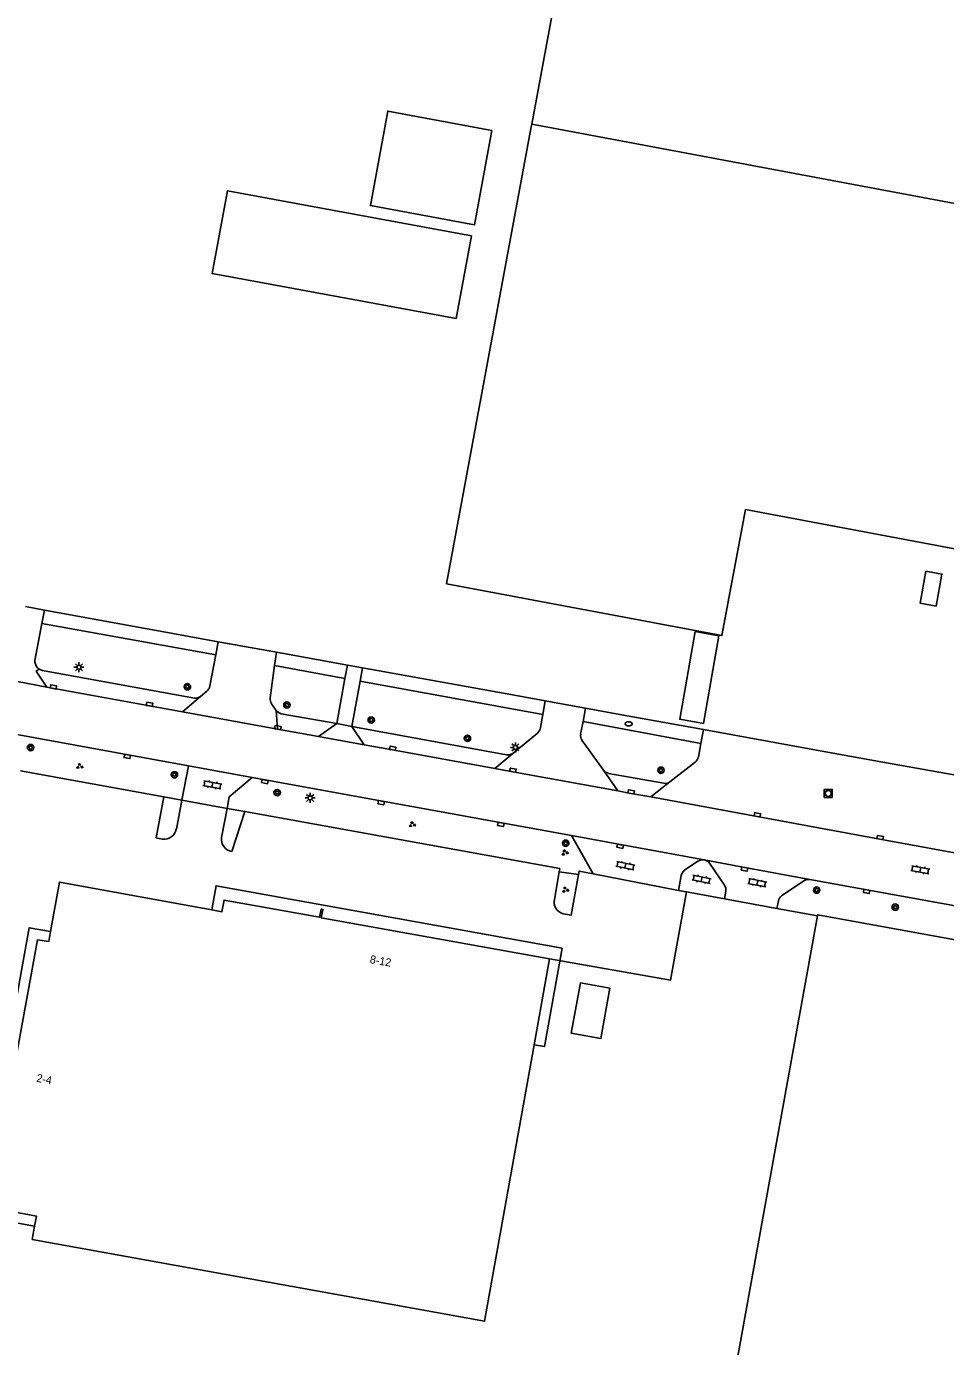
# Model space of a CAD drawing. Extents: x 130998 to 133001, y 398999 to 403002.
# Drawn here: x 132416.4 to 132531.2, y 399316.5 to 399481.4 of the extents above; entities that cross this region are included whole.
import ezdxf

# ---------------------------------------------------------------- set-up
doc = ezdxf.new("R2010")
doc.units = 0
for name, color, linetype in [('gg-afsc-hekwerk', 7, 'Continuous'), ('gg-anno-huisnummerreeks BGT', 7, 'Continuous'), ('gg-bbg-bijgebouw', 7, 'Continuous'), ('gg-bbg-gedigitaliseerde bijgebouw', 7, 'Continuous'), ('gg-bbg-hoofdgebouw', 7, 'Continuous'), ('gg-bbg-luifel en loopbrug', 7, 'Continuous'), ('gg-bbg-tussenscheiding', 7, 'Continuous'), ('gg-knt-verharding', 7, 'Continuous'), ('gg-knt-verharding nz', 7, 'Continuous'), ('gt-grn-groengrens', 7, 'Continuous'), ('gt-grn-vlakafsluiter', 7, 'Continuous'), ('gt-grn-weggrens', 7, 'Continuous'), ('gt-symb-boom', 7, 'Continuous'), ('gt-symb-brandkraan', 7, 'Continuous'), ('gt-symb-groenvak', 7, 'Continuous'), ('gt-symb-klinker verharding', 7, 'Continuous'), ('gt-symb-kolk', 7, 'Continuous'), ('gt-symb-lichtmast', 7, 'Continuous'), ('gt-symb-rioolschacht', 7, 'Continuous')]:
    doc.layers.add(name, color=color, linetype=linetype)

# ---------------------------------------------------------------- blocks, each defined once
blk = doc.blocks.new('gt0-BOOM')
at = {"layer": 'gt-symb-boom'}
for radius in [0.4, 0.2]:
    blk.add_circle((0, 0), radius, dxfattribs=at)
blk = doc.blocks.new('gt0-KOLK')
at = {"layer": 'gt-symb-kolk'}
blk.add_lwpolyline([(0, 0), (0.37, 0), (0.37, 0.4), (-0.38, 0.4), (-0.38, 0), (0, 0)], dxfattribs=at)
blk = doc.blocks.new('gt0-LMAST')
at = {"layer": 'gt-symb-lichtmast'}
for p, q in [((-0.18, 0.17), (-0.45, 0.44)), ((-0.01, 0.25), (-0.01, 0.62)), ((0.17, 0.17), (0.44, 0.44)), ((-0.26, 0), (-0.63, 0)), ((-0.18, -0.18), (-0.45, -0.45)), ((-0.01, -0.25), (-0.01, -0.63)), ((0.44, -0.45), (0.17, -0.18)), ((0.24, 0), (0.62, 0))]:
    blk.add_line(p, q, dxfattribs=at)
blk.add_circle((-0.01, 0), 0.25, dxfattribs=at)
blk = doc.blocks.new('gt0-BR')
at = {"layer": 'gt-symb-brandkraan'}
for centre, radius, start, end in [((-0.24, 0), 0.206, 107.5669, 252.4331), ((0.6, -2.66), 3, 106.892, 107.5669), ((0, -0.69), 0.938, 73.108, 106.892), ((-0.6, -2.66), 3, 72.4331, 73.108), ((0.24, 0), 0.206, 287.567, 72.4331), ((0.6, 2.66), 3, 252.4331, 253.108), ((0, 0.69), 0.938, 253.108, 286.8921), ((-0.6, 2.66), 3, 286.8921, 287.567)]:
    blk.add_arc(centre, radius, start, end, dxfattribs=at)
blk = doc.blocks.new('gt0-RS')
at = {"layer": 'gt-symb-rioolschacht'}
blk.add_lwpolyline([(-0.5, -0.5), (0.5, -0.5), (0.5, 0.5), (-0.5, 0.5)], close=True, dxfattribs=at)
blk.add_circle((0, 0), 0.375, dxfattribs=at)
blk = doc.blocks.new('gt0-GRVAK')
at = {"layer": 'gt-symb-groenvak'}
for p, q in [((-0.11, 0.19), (-0.23, 0.24)), ((-0.18, 0.15), (0.09, 0.15)), ((-0.09, 0.21), (-0.16, 0.32)), ((-0.05, 0.21), (-0.05, 0.39)), ((0, 0.21), (0.06, 0.32)), ((0.01, 0.19), (0.13, 0.24)), ((0.26, -0.05), (0.2, 0.06)), ((0.3, -0.05), (0.3, 0.13)), ((0.35, -0.05), (0.41, 0.06)), ((-0.24, -0.23), (-0.36, -0.18)), ((-0.32, -0.26), (-0.05, -0.26)), ((-0.23, -0.21), (-0.29, -0.09)), ((-0.18, -0.2), (-0.18, -0.02)), ((-0.14, -0.21), (-0.07, -0.09)), ((-0.12, -0.23), (0, -0.18)), ((0.24, -0.07), (0.12, -0.02)), ((0.17, -0.11), (0.44, -0.11)), ((0.37, -0.07), (0.49, -0.02))]:
    blk.add_line(p, q, dxfattribs=at)
blk = doc.blocks.new('gt0-KL1')
at = {"layer": 'gt-symb-klinker verharding'}
for p, q in [((-1.15, 0.3), (1.15, 0.3)), ((-1, -0.3), (-1, 0.3)), ((-0.5, 0.3), (-0.5, 0.45)), ((0, -0.3), (0, 0.3)), ((0.5, 0.3), (0.5, 0.45)), ((1, -0.3), (1, 0.3)), ((-1.15, -0.3), (1.15, -0.3)), ((-0.5, -0.45), (-0.5, -0.3)), ((0.5, -0.45), (0.5, -0.3))]:
    blk.add_line(p, q, dxfattribs=at)

msp = doc.modelspace()

# ---------------------------------------------------------------- linework, layer by layer
at = {"layer": 'gg-afsc-hekwerk'}
for p, q in [((132418.61, 399408.47), (132416.24, 399408.9)), ((132432.6, 399405.92), (132418.61, 399408.47)), ((132440.33, 399404.52), (132432.6, 399405.92)), ((132447.16, 399403.28), (132440.33, 399404.52)), ((132447.62, 399403.2), (132447.16, 399403.28)), ((132456.47, 399401.59), (132447.62, 399403.2)), ((132458.36, 399401.25), (132456.47, 399401.59)), ((132462.05, 399400.58), (132458.36, 399401.25)), ((132462.05, 399400.58), (132477.33, 399397.82)), ((132481.2, 399397.12), (132477.33, 399397.82)), ((132484.14, 399396.59), (132481.2, 399397.12)), ((132484.14, 399396.59), (132486.24, 399396.21)), ((132486.24, 399396.21), (132490.52, 399395.43)), ((132490.52, 399395.43), (132500.96, 399393.54)), ((132500.96, 399393.54), (132517.36, 399390.57)), ((132523.39, 399389.48), (132517.36, 399390.57)), ((132523.39, 399389.48), (132532.5, 399387.85)), ((132503.59, 399372.4), (132498.84, 399373.27)), ((132510.13, 399371.21), (132503.59, 399372.4)), ((132515.21, 399370.29), (132510.13, 399371.21))]:
    msp.add_line(p, q, dxfattribs=at)
msp.add_lwpolyline([(132481.74, 399364.89), (132496.83, 399362.22), (132498.84, 399373.27)], dxfattribs=at)
at = {"layer": 'gg-bbg-bijgebouw'}
msp.add_lwpolyline([(132479.5, 399469.15), (132486.41, 399506.55), (132504.29, 399503.24)], dxfattribs=at)
at = {"layer": 'gg-bbg-gedigitaliseerde bijgebouw'}
for points in [[(132474.53, 399468.38), (132461.52, 399470.79), (132459.34, 399458.99), (132472.35, 399456.58), (132474.53, 399468.38)], [(132470.05, 399444.89), (132439.57, 399450.52), (132441.48, 399460.85), (132471.96, 399455.22), (132470.05, 399444.89)]]:
    msp.add_lwpolyline(points, dxfattribs=at)
at = {"layer": 'gg-bbg-hoofdgebouw'}
for p, q in [((132515.21, 399370.29), (132501.01, 399291.82)), ((132479.81, 399354.18), (132481.74, 399364.89)), ((132417.38, 399331.51), (132417.08, 399329.85))]:
    msp.add_line(p, q, dxfattribs=at)
for points in [[(132479.5, 399469.15), (132479.45, 399468.82), (132468.86, 399411.76), (132503.27, 399405.29), (132506.22, 399421.01), (132537.65, 399415.11), (132534.89, 399400.38), (132535.88, 399400.2), (132536.06, 399401.18), (132568.46, 399395.22), (132568.28, 399394.24), (132569.27, 399394.05), (132579.82, 399450.35)], [(132439.52, 399371.03), (132420.48, 399374.48), (132419.38, 399368.31)], [(132481.74, 399364.89), (132453.21, 399370.04), (132453.42, 399371.08), (132453.2, 399371.12), (132452.98, 399370.1), (132441.07, 399372.25), (132440.8, 399370.79), (132439.52, 399371.03)], [(132515.21, 399370.29), (132515.23, 399370.38), (132564.7, 399361.42)], [(132419.38, 399368.31), (132419.15, 399367.06), (132417.77, 399367.28), (132411.63, 399333.87), (132417.61, 399332.77), (132417.38, 399331.51)], [(132417.08, 399329.85), (132473.59, 399319.63), (132479.81, 399354.18)]]:
    msp.add_lwpolyline(points, dxfattribs=at)
at = {"layer": 'gg-bbg-luifel en loopbrug'}
for points in [[(132528.76, 399413.33), (132530.75, 399412.97), (132530.03, 399408.97), (132528.04, 399409.32), (132528.76, 399413.33)], [(132500.96, 399394.29), (132502.9, 399405.24), (132499.94, 399405.77), (132497.99, 399394.82), (132500.96, 399394.29)], [(132439.52, 399371.03), (132440.07, 399374.04), (132483.3, 399366.22), (132481.08, 399353.95), (132479.81, 399354.18)], [(132417.38, 399331.51), (132410.21, 399332.8), (132416.72, 399368.79), (132419.38, 399368.31)], [(132485.58, 399361.89), (132484.44, 399355.61), (132488.14, 399354.94), (132489.28, 399361.22), (132485.58, 399361.89)]]:
    msp.add_lwpolyline(points, dxfattribs=at)
at = {"layer": 'gg-bbg-tussenscheiding'}
msp.add_line((132479.5, 399469.15), (132533.05, 399459.11), dxfattribs=at)
at = {"layer": 'gg-knt-verharding'}
for p, q in [((132418.61, 399408.47), (132418.29, 399406.79)), ((132418.29, 399406.79), (132440.02, 399402.89)), ((132440.33, 399404.52), (132440.02, 399402.89)), ((132440.02, 399402.89), (132439.27, 399399)), ((132447.62, 399403.2), (132447.37, 399401.54)), ((132447.37, 399401.54), (132446.83, 399397.5)), ((132447.37, 399401.54), (132456.17, 399399.93)), ((132455.15, 399394.28), (132456.17, 399399.93)), ((132458.07, 399399.6), (132457.03, 399393.94)), ((132480.89, 399395.41), (132458.07, 399399.6)), ((132438.9, 399398.35), (132438.13, 399397.68)), ((132447, 399396.76), (132447.58, 399395.94)), ((132480.89, 399395.41), (132481.2, 399397.12)), ((132485.92, 399394.54), (132486.24, 399396.21)), ((132448.2, 399395.51), (132455.15, 399394.28)), ((132480.59, 399393.79), (132480.89, 399395.41)), ((132485.92, 399394.54), (132485.61, 399392.96)), ((132485.92, 399394.54), (132500.64, 399391.82)), ((132436.6, 399389), (132409.08, 399394.02)), ((132457.03, 399393.94), (132476.36, 399390.4)), ((132477.13, 399390.55), (132480.22, 399393.11)), ((132500.64, 399391.82), (132500.96, 399393.54)), ((132485.78, 399392.2), (132488.45, 399388.48)), ((132500.32, 399390.1), (132500.64, 399391.82)), ((132496.76, 399387), (132499.92, 399389.45)), ((132415.64, 399388.37), (132433.52, 399385.15)), ((132436.6, 399389), (132435.79, 399384.73)), ((132489.1, 399388.07), (132496, 399386.83)), ((132444.59, 399387.55), (132484.46, 399380.29)), ((132435.79, 399384.73), (132435.1, 399381.1)), ((132441.44, 399383.7), (132440.75, 399380.04)), ((132442.04, 399378.32), (132443.67, 399383.29)), ((132443.67, 399383.29), (132483, 399376.19)), ((132484.46, 399380.29), (132487.19, 399375.52)), ((132482.93, 399375.79), (132483, 399376.19)), ((132498.61, 399375.98), (132500.27, 399377.1)), ((132501.71, 399376.86), (132503.59, 399374.09)), ((132482.29, 399372.08), (132482.93, 399375.79)), ((132497.85, 399373.44), (132498.18, 399375.33)), ((132513.52, 399374.66), (132510.72, 399372.77)), ((132521.37, 399373.52), (132514.26, 399374.83)), ((132498.84, 399373.27), (132497.85, 399373.44)), ((132503.76, 399373.35), (132503.59, 399372.4)), ((132574.22, 399364.02), (132521.37, 399373.52)), ((132510.32, 399372.16), (132510.13, 399371.21))]:
    msp.add_line(p, q, dxfattribs=at)
for points in [[(132418.29, 399406.79), (132417.41, 399402.17), (132417.43, 399401.94), (132417.6, 399401.49), (132417.76, 399401.26), (132417.95, 399401.07)], [(132437.37, 399397.47), (132418.36, 399400.92), (132417.95, 399401.07)], [(132444.59, 399387.55), (132441.71, 399385.14), (132441.44, 399383.7)], [(132433.33, 399379.86), (132432.59, 399380.01), (132433.52, 399385.15)], [(132485.36, 399375.44), (132484.43, 399370.37), (132483.73, 399370.48)], [(132487.19, 399375.52), (132485.44, 399375.86), (132485.36, 399375.44)]]:
    msp.add_lwpolyline(points, dxfattribs=at)
for centre, radius, start, end in [((132437.45, 399398.64), 1.17, 265.8248, 305.1454), ((132438.27, 399399.12), 1, 309.1204, 353.1846), ((132447.91, 399397.37), 1.09, 173.131, 214.03), ((132448.44, 399396.52), 1.04, 214.1448, 256.9701), ((132479.53, 399393.92), 1.06, 310.2604, 352.6021), ((132486.71, 399392.8), 1.1, 172.0776, 213.1245), ((132476.58, 399391.34), 0.962, 256.9989, 304.7555), ((132499.3, 399390.28), 1.03, 306.991, 350.1784), ((132489.28, 399389.1), 1.04, 216.5456, 259.9173), ((132496.17, 399387.82), 1.01, 259.9094, 305.4191), ((132433.56, 399381.42), 1.57, 261.7742, 348.3622), ((132442.25, 399379.83), 1.52, 172.042, 261.8262), ((132500.85, 399376.15), 1.12, 79.8399, 121.4525), ((132500.84, 399376.14), 1.13, 39.7007, 79.2696), ((132499.2, 399375.12), 1.04, 124.4422, 168.5855), ((132514.13, 399373.68), 1.15, 83.9663, 122.3067), ((132502.76, 399373.52), 1.01, 350.2706, 34.5089), ((132483.84, 399372.03), 1.55, 178.21, 265.9071), ((132511.45, 399371.85), 1.17, 128.5018, 164.8582)]:
    msp.add_arc(centre, radius, start, end, dxfattribs=at)
at = {"layer": 'gg-knt-verharding nz'}
for p, q in [((132407.24, 399401.11), (132418.91, 399398.82)), ((132456.17, 399399.93), (132456.47, 399401.59)), ((132458.36, 399401.25), (132458.07, 399399.6)), ((132418.91, 399398.82), (132435.86, 399395.74)), ((132438.13, 399397.68), (132435.86, 399395.74)), ((132447.58, 399395.94), (132447.74, 399393.6)), ((132435.86, 399395.74), (132447.74, 399393.6)), ((132452.88, 399392.67), (132455.15, 399394.28)), ((132455.15, 399394.28), (132457.03, 399393.94)), ((132447.74, 399393.6), (132452.88, 399392.67)), ((132452.88, 399392.67), (132458.57, 399391.64)), ((132457.03, 399393.94), (132458.57, 399391.64)), ((132474.88, 399388.67), (132477.13, 399390.55)), ((132436.6, 399389), (132444.59, 399387.55)), ((132488.45, 399388.48), (132490.27, 399385.89)), ((132494.37, 399385.13), (132496.76, 399387)), ((132501.05, 399377.25), (132484.46, 399380.29))]:
    msp.add_line(p, q, dxfattribs=at)
for points in [[(132418.91, 399398.82), (132417.59, 399400.84), (132417.95, 399401.07)], [(132458.57, 399391.64), (132462.1, 399391), (132474.88, 399388.67)], [(132474.88, 399388.67), (132477.13, 399388.27), (132490.27, 399385.89)], [(132490.27, 399385.89), (132491.9, 399385.57), (132494.37, 399385.13)], [(132494.37, 399385.13), (132507.66, 399382.7), (132522.99, 399379.86), (132535.28, 399377.62)], [(132514.26, 399374.83), (132506.11, 399376.31), (132501.05, 399377.25)]]:
    msp.add_lwpolyline(points, dxfattribs=at)
at = {"layer": 'gt-grn-groengrens'}
for p, q in [((132435.79, 399384.73), (132433.52, 399385.15)), ((132443.67, 399383.29), (132441.44, 399383.7)), ((132482.93, 399375.79), (132485.36, 399375.44))]:
    msp.add_line(p, q, dxfattribs=at)
at = {"layer": 'gt-grn-vlakafsluiter'}
msp.add_line((132487.19, 399375.52), (132497.85, 399373.44), dxfattribs=at)
at = {"layer": 'gt-grn-weggrens'}
msp.add_line((132441.44, 399383.7), (132435.79, 399384.73), dxfattribs=at)

# ---------------------------------------------------------------- block references
at = {"layer": 'gt-symb-boom'}
for p in [(132436.48, 399398.89), (132448.91, 399396.61), (132459.45, 399394.73), (132471.47, 399392.45), (132416.89, 399391.29), (132434.86, 399387.9), (132495.65, 399388.46), (132447.7, 399385.66), (132483.75, 399379.34), (132515.1, 399373.49), (132524.92, 399371.36)]:
    msp.add_blockref('gt0-BOOM', p, dxfattribs=at)
at = {"layer": 'gt-symb-brandkraan'}
msp.add_blockref('gt0-BR', (132491.61, 399394.25), dxfattribs=at)
at = {"layer": 'gt-symb-groenvak'}
for p, rotation in [((132423, 399388.95), -9.905079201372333), ((132464.56, 399381.68), -9.905079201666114)]:
    msp.add_blockref('gt0-GRVAK', p, dxfattribs=dict(at, rotation=rotation))
for p in [(132483.63, 399378.16), (132483.69, 399373.52)]:
    msp.add_blockref('gt0-GRVAK', p, dxfattribs=at)
at = {"layer": 'gt-symb-klinker verharding'}
for p, rotation in [((132439.6, 399386.64), -10.489389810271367), ((132491.2, 399376.53), -11.186329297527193), ((132528.05, 399376.03), -10.489389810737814), ((132500.72, 399374.84), -11.18632930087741), ((132507.68, 399374.4), -11.186329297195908)]:
    msp.add_blockref('gt0-KL1', p, dxfattribs=dict(at, rotation=rotation))
at = {"layer": 'gt-symb-kolk'}
for p, rotation in [((132419.7, 399398.67), -10.25359802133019), ((132431.72, 399396.49), -10.30997039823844), ((132447.74, 399393.58), -10.369807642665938), ((132462.1, 399391), -10.369807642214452), ((132429, 399390.37), 169.69002960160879), ((132477.13, 399388.27), -10.369807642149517), ((132446.19, 399387.24), 169.21838326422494), ((132491.9, 399385.57), -10.369807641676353), ((132460.72, 399384.6), 169.6336773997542), ((132507.66, 399382.7), -10.369807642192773), ((132475.67, 399381.88), 169.63367739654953), ((132523.01, 399379.86), -10.369807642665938), ((132490.58, 399379.16), 169.65545752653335), ((132506.11, 399376.31), 169.704536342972), ((132521.37, 399373.52), 169.63367739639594)]:
    msp.add_blockref('gt0-KOLK', p, dxfattribs=dict(at, rotation=rotation))
at = {"layer": 'gt-symb-lichtmast'}
for p in [(132422.94, 399401.32), (132477.47, 399391.32), (132451.83, 399385.01)]:
    msp.add_blockref('gt0-LMAST', p, dxfattribs=at)
at = {"layer": 'gt-symb-rioolschacht'}
msp.add_blockref('gt0-RS', (132516.55, 399385.56), dxfattribs=at)

# ---------------------------------------------------------------- texts
at = {"layer": 'gg-anno-huisnummerreeks BGT'}
for s, rotation, p in [('8-12', 349.7, (132459.22, 399364.39)), ('2-4', 349.6, (132417.55, 399349.56))]:
    msp.add_text(s, height=1, rotation=rotation, dxfattribs=at).set_placement(p)

doc.saveas('drawing.dxf')
